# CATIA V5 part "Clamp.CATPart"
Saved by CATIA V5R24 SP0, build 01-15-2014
Part number: Clamp
Bounding box of the stored display mesh (mm): x -20 to 20, y -57.322 to 9.761, z -161.013 to 7.887
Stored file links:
  C:\Users\minsi\Google 드라이브\CDL_2019\00_CLASS\00_CAD\기말고사\DMU\Clamp.CATPart
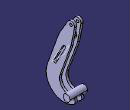
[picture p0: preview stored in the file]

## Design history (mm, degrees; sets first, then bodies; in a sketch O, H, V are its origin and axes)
Body1 (main body)
  Sketch1 on yz-plane, origin (0, 0, 0), H (0, 1, 0), V (0, 0, 1)
    line L1 (-6.8511, 4.1307) -> (-27.1778, -29.5832)
    line L2 (-27.1778, -29.5832) -> (-54.8561, -105.6287)
    arc A1 centre (-16.075, -119.7439) radius 41.27 from (-54.8561, -105.6287) to (6.1267, -154.5333) ccw
    arc A2 centre (1.823, -147.7895) radius 8 from (6.1267, -154.5333) to (0, -140) ccw
    point P7 (0, -140)
    arc A3 centre (-4.9754, -118.837) radius 21.74 from (0, -140) to (-25.4043, -111.4015) cw
    line L3 (-25.4043, -111.4015) -> (0, -41.6037)
    line L4 (0, -41.6037) -> (7.8507, -1.5383)
    arc A4 centre (0, 0) radius 8 from (7.8507, -1.5383) to (-6.8511, 4.1307) ccw
    point P12 (0, 0)
    radius A4 = 8
    radius A1 = 41.27
    angle L1 L4 = 20
    distance L2 L3 = 29.65
    angle L3 V = 20
    radius A3 = 21.74
    distance P7 H = 140
    radius A2 = 8
    tangency: A1 L2, A2 A1, A3 A2, L3 A3, A4 L4, L1 A4
    coincidence: P12 O, P7 V
  Pad1: profile Sketch1, direction (1, 0, 0), length 10, mirrored extent
  Sketch2 on end face of Pad1, origin (10, -2.9749, -10.511), H (0, 1, 0), V (0, 0, 1)
    point P1 (2.9749, 10.511)
    reference projected arc E1 centre (2.9749, 10.511) radius 8 from (10.8534, 9.1218) to (-3.9533, 14.511) ccw from edge [face of Pad1 from Sketch1.A4 | end face of Pad1]
    concentricity: E1 P1
  Hole1: placed by Sketch2, at (10, 0, 0) direction (-1, 0, 0), diameter 6, through (limit type 3)
  Sketch3 on zx-plane, origin (0, 0, 0), H (-1, 0, 0), V (0, 0, 1)
    line L1 (-5, 37.0654) -> (5, 37.0654)
    line L2 (5, 37.0654) -> (5, -186.1829)
    line L3 (5, -186.1829) -> (-5, -186.1829)
    line L4 (-5, -186.1829) -> (-5, 37.0654)
    reference projected line E1 (10, -41.6037) -> (10, -1.5383) from edge [start face of Pad1 | face of Pad1 from Sketch1.L4]
    distance L2 E1 = 5
    horizontal: L1 H, L3 H
    vertical: L2 V, L4 V
    symmetry: L4 L2 V
  Pocket1: profile Sketch3, direction (0, -1, 0), through (limit type 3), opposite side through (limit type 3)
  Sketch4 on yz-plane, origin (0, 0, 0), H (0, 1, 0), V (0, 0, 1)
    construction line L1 (-15.63, -50.92) -> (-36.65, -90.71)
    point P1 (-15.63, -50.92)
    point P2 (-36.65, -90.71)
    line L2 (-12.9774, -52.3213) -> (-33.9974, -92.1113)
    line L3 (-39.3026, -89.3087) -> (-18.2826, -49.5187)
    arc A1 centre (-36.65, -90.71) radius 3 from (-33.9974, -92.1113) to (-39.3026, -89.3087) cw
    arc A2 centre (-15.63, -50.92) radius 3 from (-18.2826, -49.5187) to (-12.9774, -52.3213) cw
    distance L1 L2 = 3
    distance P1 H = 50.92
    distance P1 V = 15.63
    distance P2 H = 90.71
    distance P2 V = 36.65
    tangency: A1 L2, A2 L2, A1 L3, A2 L3
  Pocket2: profile Sketch4, direction (-1, 0, 0), through (limit type 3), opposite side through (limit type 3)
  Sketch5 on yz-plane, origin (0, 0, 0), H (0, 1, 0), V (0, 0, 1)
    circle A1 centre (-10.26, -28.19) radius 9
    point P1 (-10.26, -28.19)
    circle A2 centre (-41, -111.26) radius 9
    point P2 (-41, -111.26)
    radius A1 = 9
    distance P1 H = 28.19
    distance P1 V = 10.26
    radius A2 = 9
    distance P2 H = 111.26
    distance V P2 = 41
  Pad2: profile Sketch5, direction (1, 0, 0), up to the existing solid (limit type 2), opposite side up to the existing solid (limit type 2)
  Sketch6 on yz-plane, origin (0, 0, 0), H (0, 1, 0), V (0, 0, 1)
    circle A1 centre (0, -140) radius 8
    point P1 (0, -140)
    radius A1 = 8
    distance P1 H = 140
    coincidence: P1 V
  Pad3: profile Sketch6, direction (1, 0, 0), length 20, mirrored extent
  Plane1: type Offset, RefPlane face of Pocket2 from Sketch4.L3, Offset 3, reversed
